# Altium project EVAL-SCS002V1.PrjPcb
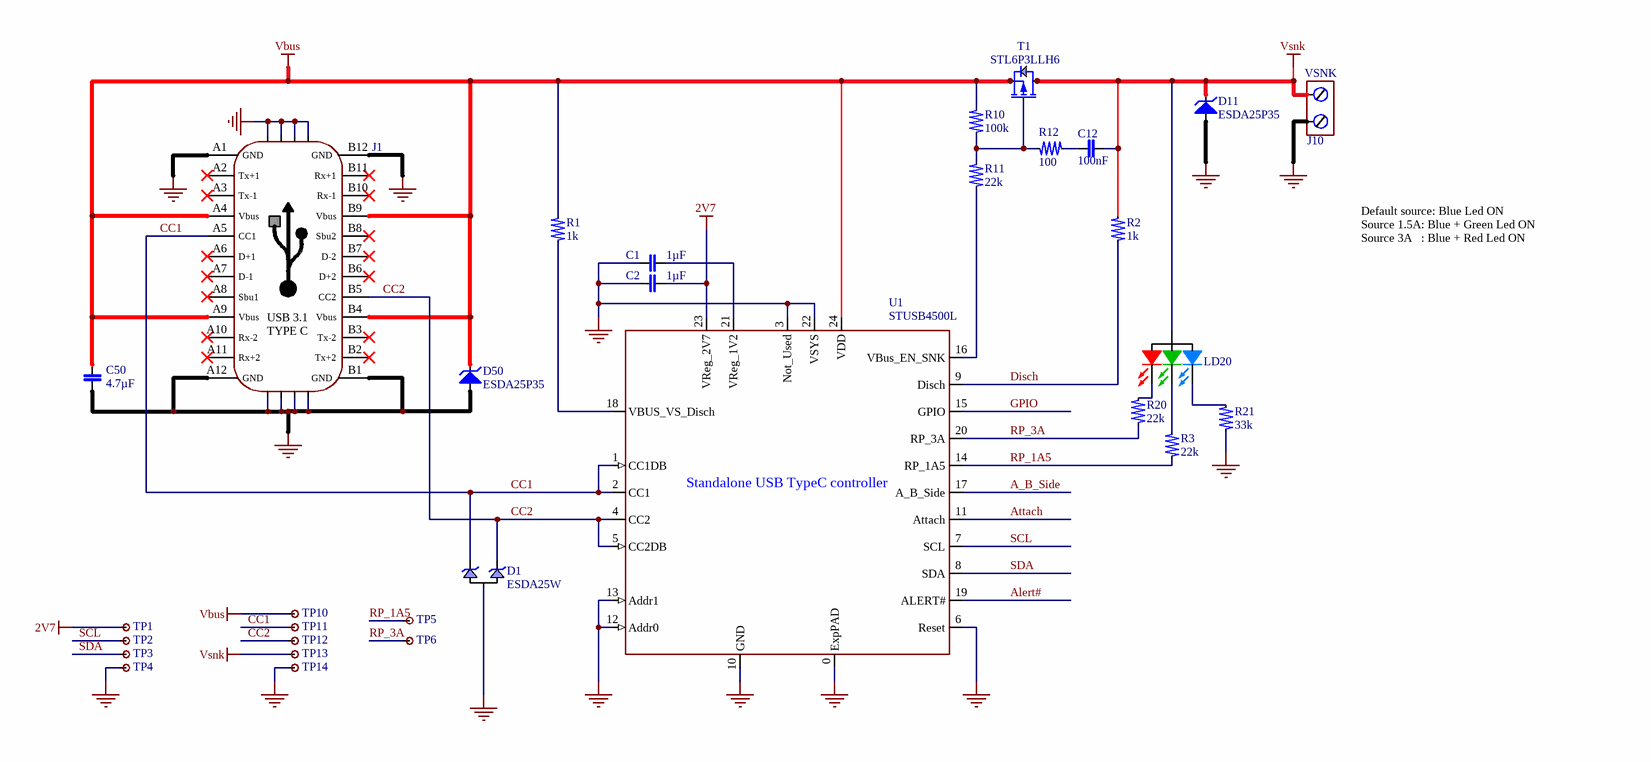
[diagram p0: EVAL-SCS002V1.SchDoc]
1 sheet, 31 parts. Net scope: global (net labels, ports and power ports of the same name join across sheets).
Board file: EVAL-SCS002V1.PcbDoc

## Sheet EVAL-SCS002V1.SchDoc: EVAL-SCS002V1
size 420 x 297 mm; PageSetup: Record=PageOptions¦CenterHorizontal=True¦CenterVertical=True¦PrintScale=0.70¦XCorrection=1.00¦YCorrection=1.00¦PrintKind=0¦BorderSize=5000000¦LeftOffset=0¦BottomOffset=0¦Orientation=2¦PaperLength=1000¦PaperWidth=1000¦Scale=100¦PaperSource=7¦PrintQuality=600¦MediaType=1¦DitherType=10¦PaperKind=A4¦PrintScaleMode=1; Organization: ST-Microelectronics; Address1: Analog, MEMS & Sensors; Address2: 12, rue Jules Horowitz; Address3: BP217; Address4: F - 38059 GRENOBLE; Revision: 1; SheetNumber: 1; SheetTotal: 1; Version: 1; SchematicTitle: EVAL-SCS002V1

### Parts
C1  1µF  [CAPC1005N]
C2  1µF  [CAPC1005N]
C12  100nF  [CAPC1005N]
C50  4.7µF  [CAPC2012N]
D1  ESDA25W  [SOT323-3L]
D11  ESDA25P35  [QFN1610]
D50  ESDA25P35  [QFN1610]
J1  USB_3.1_TypeC_Receptacle_1.6mm  [USB3 C - SMT et T - H - F - WURTH - 632723X00011]  (value not drawn)
J10  VSNK  [MPT_0.5_2-2.54]
LD20  RGB  [LED_0606_RGB_WURTH]  (value not drawn)
R1  1k  [RESC1608N]
R2  1k  [RESC1608N]
R3  22k  [RESC1005N]
R10  100k  [RESC1005N]
R11  22k  [RESC1005N]
R12  100  [RESC1005N]
R20  22k  [RESC1005N]
R21  33k  [RESC1005N]
T1  STL6P3LLH6  [PowerFLAT_3.3x3.3_F]
TP1  TestPoint  [TestPoint_SMD_1.27mm]  (value not drawn)  (no BOM)
TP2  TestPoint  [TestPoint_SMD_1.27mm]  (value not drawn)  (no BOM)
TP3  TestPoint  [TestPoint_SMD_1.27mm]  (value not drawn)  (no BOM)
TP4  TestPoint  [TestPoint_SMD_1.27mm]  (value not drawn)  (no BOM)
TP5  TestPoint  [TestPoint_SMD_1.27mm]  (value not drawn)  (no BOM)
TP6  TestPoint  [TestPoint_SMD_1.27mm]  (value not drawn)  (no BOM)
TP10  TestPoint  [TestPoint_SMD_1.27mm]  (value not drawn)  (no BOM)
TP11  TestPoint  [TestPoint_SMD_1.27mm]  (value not drawn)  (no BOM)
TP12  TestPoint  [TestPoint_SMD_1.27mm]  (value not drawn)  (no BOM)
TP13  TestPoint  [TestPoint_SMD_1.27mm]  (value not drawn)  (no BOM)
TP14  TestPoint  [TestPoint_SMD_1.27mm]  (value not drawn)  (no BOM)
U1  STUSB4500L  [QFN24 - 4X4mm - pitch 0.5mm - ExposedPAD]

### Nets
2V7: C2.2 TP1.0 U1.23(VReg_2V7)
GND: C1.1 C2.1 C50.2 D1.3(A) D11.2(A) D50.2(A) J1.A1(GND) J1.A12(GND) J1.B1(GND) J1.B12(GND) J1.G1 J1.G2 J1.G3 J1.G4 J1.G5 J1.G6 J1.G7 J1.G8 J10.1 R21.2 TP4.0 TP14.0 U1.0(ExpPAD) U1.3(Not_Used) U1.6(Reset) U1.10(GND) U1.12(Addr0) U1.13(Addr1) U1.22(VSYS)
Vbus: C50.1 D50.1(K) J1.A4(Vbus) J1.A9(Vbus) J1.B4(Vbus) J1.B9(Vbus) R1.2 R10.1 T1.1(S1) T1.2(S2) T1.3(S3) TP10.0 U1.24(VDD)
Vsnk: C12.2 D11.1(K) J10.2 LD20.A R2.1 T1.5(D1) T1.6(D2) T1.7(D3) T1.8(D4) TP13.0
A_B_Side: U1.17(A_B_Side)
Alert#: U1.19(ALERT#)
Attach: U1.11(Attach)
CC1: D1.2(K2) J1.A5(CC1) TP11.0 U1.1(CC1DB) U1.2(CC1)
CC2: D1.1(K1) J1.B5(CC2) TP12.0 U1.4(CC2) U1.5(CC2DB)
Disch: R2.2 U1.9(Disch)
GPIO: U1.15(GPIO)
RP_1A5: R3.2 TP5.0 U1.14(RP_1A5)
RP_3A: R20.2 TP6.0 U1.20(RP_3A)
SCL: TP2.0 U1.7(SCL)
SDA: TP3.0 U1.8(SDA)
NetC1_2: C1.2 U1.21(VReg_1V2)
NetC12_1: C12.1 R12.2
NetLD20_BK: LD20.BK R21.1
NetLD20_GK: LD20.GK R3.1
NetLD20_RK: LD20.RK R20.1
NetR1_1: R1.1 U1.18(VBUS_VS_Disch)
NetR10_2: R10.2 R11.1 R12.1 T1.4(G)
NetR11_2: R11.2 U1.16(VBus_EN_SNK)

Not connected (* = marked no-connect by the designer): J1 A2(Tx+1)* A3(Tx-1)* A6(D+1)* A7(D-1)* A8(Sbu1)* A10(Rx-2)* A11(Rx+2)* B2(Tx+2)* B3(Tx-2)* B6(D+2)* B7(D-2)* B8(Sbu2)* B10(Rx-1)* B11(Rx+1)*

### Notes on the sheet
- Default source: Blue Led ON
  Source 1.5A: Blue + Green Led ON
  Source 3A   : Blue + Red Led ON

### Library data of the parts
C1 C2 = C_1uF_X5R_6V3_20p_0402: Capacitor 1µF X5R 6V3 20% 0402; Manufacturer: Würth Elektronik; Manufacturer’s ordering code: 885012105006; Order Code RS: 839-1641
C12 = C_100nF_X5R_25V_20p_0402: Capacitor 100nF X5R 25V 20% 0402; Manufacturer: Würth Elektronik; Manufacturer’s ordering code: 885012105018; Order Code RS: 839-1685
C50 = C_4.7uF_X7R_25V_20p_0805: Capacitor 4.7µF X7R 25V 20% 0805; Manufacturer: Würth Elektronik; Manufacturer’s ordering code: 885012107018
D1 = ESDA25W: Dual Transil Array For ESD Protection in SOT323 Vbr = 25V; Manufacturer: STMicroelectronics; Order Code RS: 250-117; Value: 25V TRANSIL SOT323
D11 D50 = ESDA25P35-1U1M: High power transient voltage suppressor Vbr = 24.6V; Manufacturer: STMicroelectronics; Value: 22V; Order Code RS: 163-9774
J1 = USB_3.1_TypeC_Receptacle_1.6mm: USB 3.1 Type C Receptacle Horizontal THR WR-COM 1.6mm PCB thickness; Manufacturer’s ordering code: 632723300011; Manufacturer: Würth Elektronik
J10 = MPT_0.5_2-2.54: 2 way PCB vertical mount SCREW terminal, 2.54mm; Manufacturer: Würth Elektronik; Manufacturer’s ordering code: 691210910002; Alternate Manufacturer: Phoenix Contact; Alternate Manufacturer Code: MPT 0.5/2-2.54; misc: JK308-2.54-2P
LD20 = Led_RGB_0606: RGB Led 1.6 x 1.6 mm Diffused; Manufacturer: Würth Elektronik; Manufacturer’s ordering code: 150066M153000
R1 R2 = R_0603_5percent: 5% 0603 SMD resistor
R3 R10-R12 R20 R21 = R_0402_5percent: 5% 0402 SMD resistor
T1 = STL6P3LLH6: P-channel 40 V, 0.0175 Ω typ.,8 A, STripFET™ F6  Power MOSFET in a PowerFLAT™ 3.3 x 3.3 package; Manufacturer: STMicroelectronics; Part Number: P-channel 30 V, 0.024 Ohm typ., 6 A STripFET H6 Power MOSFET in a PowerFLAT 3.3 x 3.3 package
TP1-TP6 TP10-TP14 = TestPoint_SMD
U1 = STUSB4500LQTR: Standalone USB PD controller  with SINK auto-run mode in QFN24 4x4mm; Manufacturer: STMicroelectronics; Manufacturer’s ordering code: STUSB4500QTR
